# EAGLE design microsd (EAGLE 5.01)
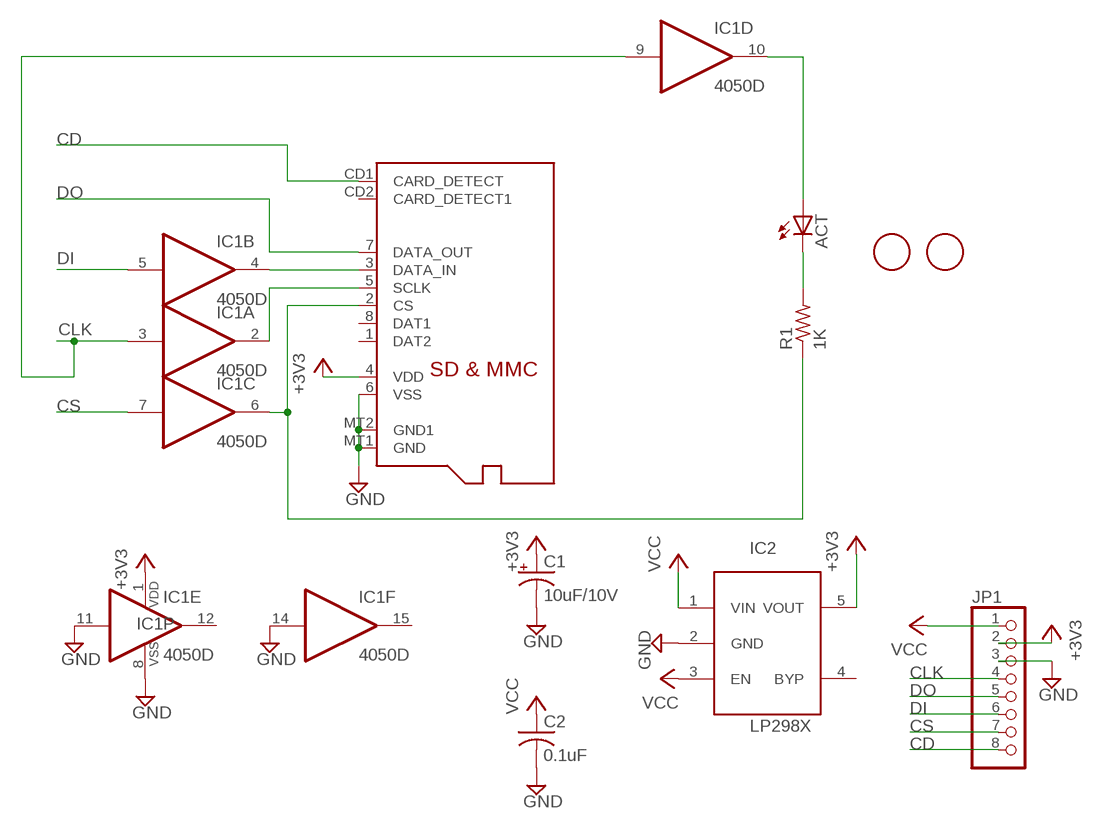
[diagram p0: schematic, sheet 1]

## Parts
ACT  LEDCHIP-LED0805  [CHIP-LED0805]
C1  10uF/10V  CPOL-USA/3216-18R  [A/3216-18R]
C2  0.1uF  C-USC0805K  [C0805K]
IC1  4050D  [SO16]
IC2  LP298XS  [SOT23-5L]
JP1  PINHD-1X8BIG  [1X08-BIG]
R1  1K  R-US_R0805  [R0805]
U$1  FIDUCIAL  [FIDUCIAL_1MM]
U$2  FIDUCIAL  [FIDUCIAL_1MM]
X1  MICROSD  [MICROSD]

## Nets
+3V3: C1.+ IC1.1(P:VDD) IC2.5(VOUT) JP1.2 X1.4(VDD)
CD: JP1.8 X1.CD1(CARD_DETECT)
CLK: IC1.3(A:I) IC1.9(D:I) JP1.4
CS: IC1.7(C:I) JP1.7
DI: IC1.5(B:I) JP1.6
DO: JP1.5 X1.7(DATA_OUT)
GND: C1.- C2.2 IC1.8(P:VSS) IC1.11(E:I) IC1.14(F:I) IC2.2(GND) JP1.3 X1.6(VSS) X1.MT1(GND) X1.MT2(GND1)
N$1: ACT.A IC1.10(D:O)
N$2: IC1.2(A:O) X1.5(SCLK)
N$3: IC1.6(C:O) R1.1 X1.2(CS)
N$4: ACT.C R1.2
N$5: IC1.4(B:O) X1.3(DATA_IN)
VCC: C2.1 IC2.1(VIN) IC2.3(EN) JP1.1
Unconnected: IC1.12(E:O) IC1.15(F:O) IC2.4(BYP) X1.1(DAT2) X1.8(DAT1) X1.CD2(CARD_DETECT1)

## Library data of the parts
ACT = adafruit:LED: LED
C1 = adafruit:CPOL-US: POLARIZED CAPACITOR, American symbol
C2 = adafruit:C-US: CAPACITOR, American symbol
IC1 = 40xx:4050: Hex non-inverting BUFFER
IC2 = adafruit:LP298X
JP1 = adafruit:PINHD-1X8: PIN HEADER
R1 = adafruit:R-US_: RESISTOR, American symbol
U$1 U$2 = adafruit:FIDUCIAL: For use by pick and place machines to calibrate the vision/machine, 1mm
X1 = adafruit:MICROSD: Micro-SD / Transflash card holder with SPI pinout For the 3M # 2908-05WB-MG and/or 4UCON #19656 push-push type

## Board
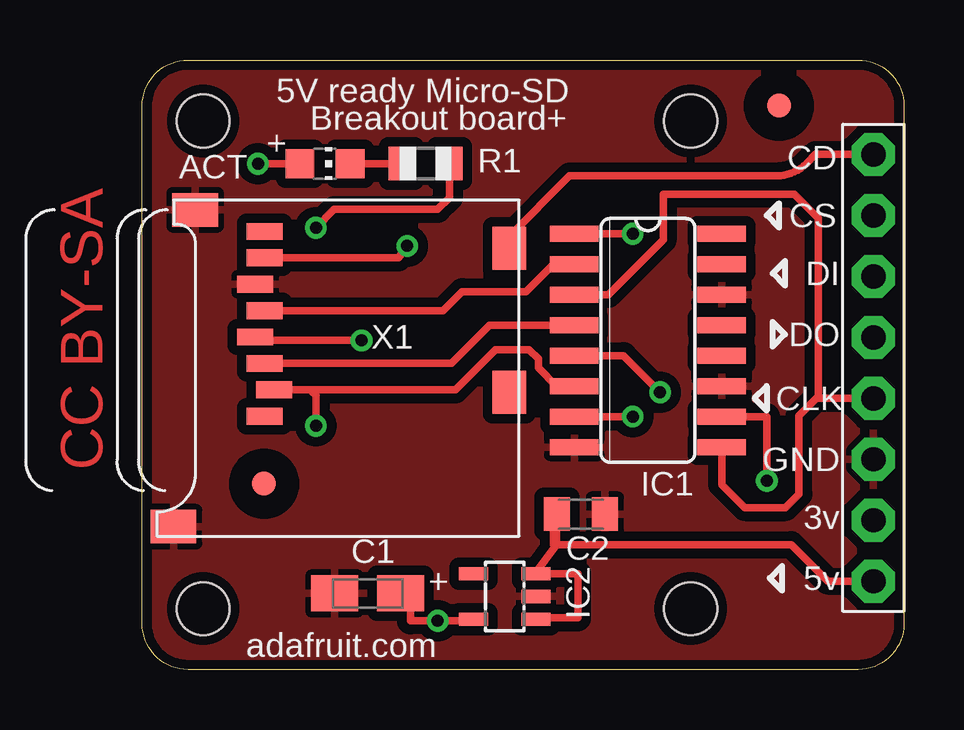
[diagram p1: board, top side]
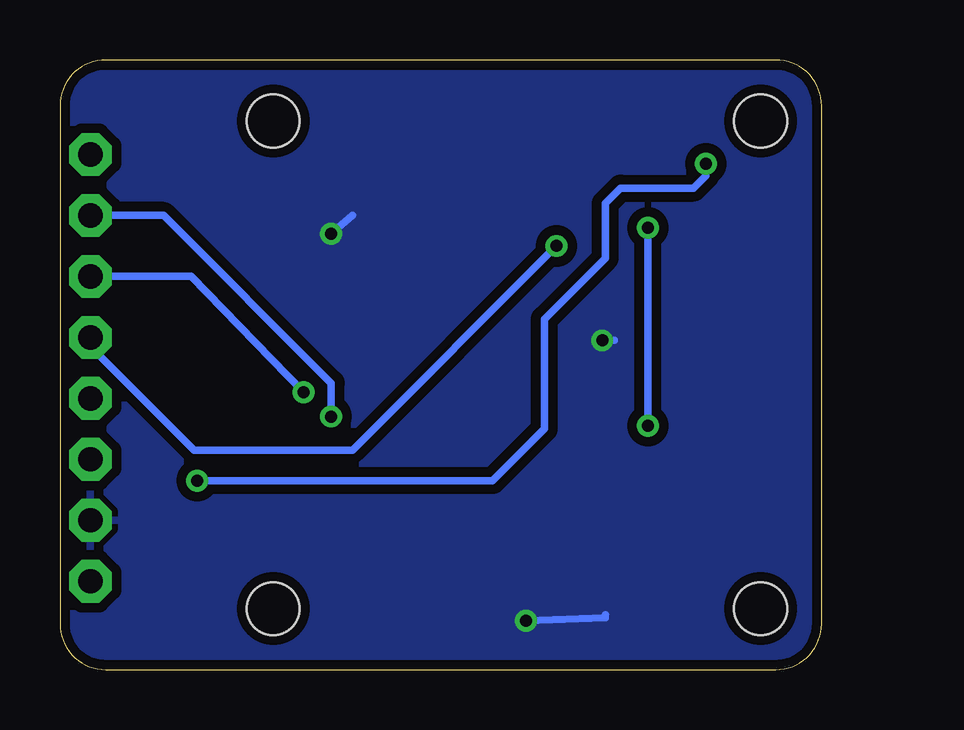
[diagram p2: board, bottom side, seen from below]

Size 31.75 x 25.4 mm. Coordinates in mm from the lower left corner, seen from the top.
Outline: 31.75,1.91 arc-90 29.84,0 1.91,0 arc-90 0,1.91 0,23.5 arc-90 1.91,25.4 29.84,25.4 arc-90 31.75,23.5 31.75,1.91
Copper layers (1*16): Top 0.035mm / dielectric 1.5mm / Bottom 0.035mm
Design rules "default *": minimum track width 12mil, minimum drill 19mil, track to track 12mil, track to pad 12mil, pad to pad 12mil, via to via 12mil, smd to smd 0mil, copper to edge 10mil, drill to drill 8mil, minimum pad ring 10mil, minimum via ring 8mil, stop-mask expansion 4mil, vias tented up to drill 20mil, thermal gap 10mil
Holes 2.2 mm at 2.54,22.86 2.54,2.54 22.86,22.86 22.86,2.54

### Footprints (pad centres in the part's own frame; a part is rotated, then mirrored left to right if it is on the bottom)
CHIP-LED0805 = smd 1.2 x 1.2: A 0,-1.05; C 0,1.05
A/3216-18R = smd 1.95 x 1.5: + 1.375,0; - -1.375,0
C0805K = smd 1.1 x 1.4: 1 -1,0; 2 1,0
SO16 = smd 0.66 x 2.032: 1 -4.445,-3.073; 2 -3.175,-3.073; 3 -1.905,-3.073; 4 -0.635,-3.073; 5 0.635,-3.073; 6 1.905,-3.073; 7 3.175,-3.073; 8 4.445,-3.073; 9 4.445,3.073; 10 3.175,3.073; 11 1.905,3.073; 12 0.635,3.073; 13 -0.635,3.073; 14 -1.905,3.073; 15 -3.175,3.073; 16 -4.445,3.073
SOT23-5L = smd 0.55 x 1.2: 1 -0.95,-1.3; 2 0,-1.3; 3 0.95,-1.3; 4 0.95,1.3; 5 -0.95,1.3
1X08-BIG = drill 1.016 pad 1.778 octagon: 1 -8.89,0; 2 -6.35,0; 3 -3.81,0; 4 -1.27,0; 5 1.27,0; 6 3.81,0; 7 6.35,0; 8 8.89,0
R0805 = smd 1.1 x 1.4: 1 -1,0; 2 1,0
FIDUCIAL_1MM = smd 1 x 1: 1 0,0
MICROSD = smd 0.7 x 1.5: 1 9,-10.64; 2 7.9,-10.24; 3 6.8,-10.64; 4 5.7,-11.04; 5 4.6,-10.64; 6 3.5,-11.04; 7 2.4,-10.64; 8 1.3,-10.64 | smd 1.8 x 1.4: CD1 2,-0.44; CD2 8,-0.44 | smd 1.4 x 1.9: MT1 0.4,-13.54; MT2 13.6,-14.44

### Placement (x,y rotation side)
ACT  7.62,21.08 270 top
C1  9.4,3.17 0 top
C2  18.29,6.48 0 top
IC1  21.08,13.72 270 top
IC2  15.11,3.05 90 top
JP1  30.48,12.57 90 top
R1  11.81,21.08 180 top
U$1  5.08,7.75 0 top
U$2  26.54,23.5 0 top
X1  15.75,19.56 270 top

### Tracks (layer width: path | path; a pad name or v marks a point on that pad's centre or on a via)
+3V3  (via drill 0.5)
  Top 0.305: IC1.1 v20.45,18.16 | X1.4 4.72,13.72 v9.14,13.72 | v12.32,2.03 12.35,2.03 | IC2.5 13.75,2.03 v12.32,2.03 | C1.+ 11.18,3.17 11.18,2.03 v12.32,2.03
  Bottom 0.305: v20.45,18.16 19.56,18.92 | v9.14,13.72 8.64,13.72 | v12.32,2.03 9.02,2.16 9.02,2.29
  pour Bottom (isolate 0.406): 0,25.4 0,0 30.1,0 arc90 31.88,1.78 31.88,25.4
CD
  Top 0.305: X1.CD1 15.24,17.27 15.24,18 17.82,20.57 26.44,20.57 arc45 27.7,21.09 28.07,21.46 JP1.8 30.86,21.46
CLK
  Top 0.305: IC1.3 19.43,15.62 21.72,17.91 21.72,19.81 27.18,19.81 28.19,18.8 28.19,11.3 | 30.73,11.3 JP1.4 28.19,11.3 | IC1.9 24.16,7.71 25.12,6.75 26.81,6.75 27.38,7.32 27.38,10.59 28.11,11.32 28.13,11.3 28.19,11.3
CS  (via drill 0.5)
  Top 0.305: IC1.7 v20.45,10.54
  Bottom 0.305: v20.45,10.54 20.45,11.94 27.43,18.92 28.83,18.92 JP1.7 30.73,18.92
DI  (via drill 0.5)
  Top 0.305: v21.59,11.56 20.07,13.08 18.09,13.08 18.01,13.16 | 18.01,13.16 18,13.17 | IC1.5 18.01,13.16
  Bottom 0.305: v21.59,11.56 26.29,16.38 JP1.6
DO  (via drill 0.5)
  Top 0.305: X1.7 10.68,17.16 v11.05,17.65
  Bottom 0.305: v11.05,17.65 19.56,9.14 26.16,9.14 30.73,13.72 30.73,13.84 JP1.5
GND
  pour Top (isolate 0.406): -0.13,25.4 -0.13,0 31.75,0 31.75,25.4
N$1  (via drill 0.5)
  Top 0.305: v4.83,21.08 ACT.A | IC1.10 26.04,10.54 v26.04,7.87
  Bottom 0.305: v26.04,7.87 13.72,7.87 11.56,10.03 11.56,14.61 9.02,17.14 9.02,19.43 8.38,20.07 5.33,20.07 4.83,20.57 v4.83,21.08
N$2
  Top 0.305: X1.5 12.54,14.96 13.34,15.75 16,15.75 17.14,16.89 IC1.2 18.16,16.89
N$3  (via drill 0.5)
  Top 0.305: X1.2 7.11,11.66 | 7.11,11.66 13.05,11.66 14.73,13.34 16.13,13.34 16.51,12.95 16.51,12.57 17.27,11.81 18.16,11.81 | 18.16,11.81 IC1.6 | 18.16,11.81 18.29,11.94 | R1.1 12.81,19.67 12.32,19.18 8,19.18 v7.24,18.41 | 7.11,11.66 7.11,11.56 7.24,11.43 v7.24,10.16
  Bottom 0.305: v7.24,10.16 v7.24,18.41
N$4
  Top 0.305: R1.2 10.81,21.19 10.79,21.21 10.67,21.08 ACT.C
N$5
  Top 0.305: X1.3 12.88,12.76 14.48,14.35 IC1.4
VCC
  Top 0.305: JP1.1 28.57,3.68 27.05,5.21 17.27,5.21 | 17.27,5.21 17.14,5.21 17.14,6.35 17.27,6.48 C2.1 17.27,5.21 | IC2.1 16.51,2.1 16.51,2.16 18.16,2.16 18.16,4 IC2.3 16.38,4 17.27,5.21

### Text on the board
Top: CC BY-SA
tPlace: 5V ready Micro-SD | Breakout board+ | adafruit.com
tNames: CD | CS | DI | DO | CLK | GND | 3v | 5v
